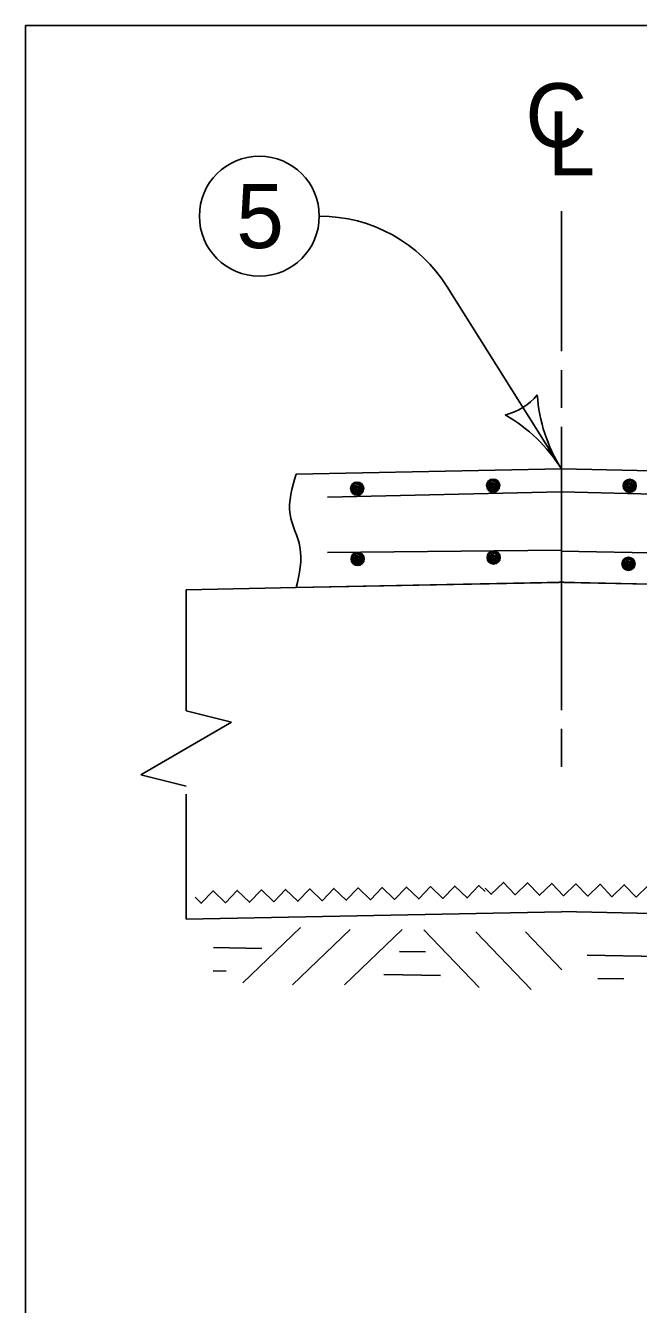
# Model space of a CAD drawing. Extents: x 10130 to 81668, y 5440 to 21644.
# Drawn here: x 17332.5 to 17485.9, y 9624 to 9944 of the extents above; entities that cross this region are included whole.
import ezdxf

# ---------------------------------------------------------------- set-up
doc = ezdxf.new("R2010")
doc.units = 0
for name, color, linetype in [('dsnStdBlockModified', 7, 'Continuous'), ('dsnStdBlockNotModified', 7, 'Continuous'), ('dsnStdBorder', 7, 'Continuous'), ('Level 2', 7, 'Continuous'), ('SheetBorder', 7, 'Continuous')]:
    doc.layers.add(name, color=color, linetype=linetype)

msp = doc.modelspace()

# ---------------------------------------------------------------- linework, layer by layer
at = {"layer": 'dsnStdBlockModified'}
msp.add_line((18198.1, 9797.36), (17466.58, 9812.52), dxfattribs=at)
at = {"layer": 'dsnStdBlockNotModified'}
msp.add_line((17438.06, 9878.61), (17466.63, 9833.07), dxfattribs=at)
for centre, radius, start, end in [((17406.03, 9858.53), 37.81, 32.09, 90), ((17448.73, 9861.6), 15.52, 284.3569, 319.8236), ((17500.66, 9854.41), 40.18, 184.0178, 212.0903), ((17432.59, 9811.72), 40.18, 32.0903, 60.1628)]:
    msp.add_arc(centre, radius, start, end, dxfattribs=at)
at = {"layer": 'dsnStdBorder'}
for p, q in [((17466.62, 9833.07), (17400.24, 9831.73)), ((17466.62, 9833.07), (17400.24, 9831.73)), ((18176.88, 9818.81), (17466.62, 9833.07)), ((17466.62, 9833.07), (18176.88, 9818.81)), ((17466.59, 9827.31), (17408.07, 9826.01)), ((17466.59, 9827.31), (18198.18, 9809.65)), ((17466.59, 9812.75), (17408.06, 9812.12)), ((17400.24, 9803.37), (17372.68, 9802.81)), ((17372.68, 9802.81), (17372.68, 9772.55)), ((17467.19, 9804.71), (17400.24, 9803.37)), ((17400.24, 9803.37), (17466.05, 9804.69)), ((17466.05, 9804.71), (17466.62, 9804.7)), ((17466.05, 9804.71), (18215.16, 9789.67)), ((17466.62, 9804.7), (17467.19, 9804.71)), ((17467.19, 9804.69), (18215.16, 9789.67)), ((17372.68, 9772.55), (17384.03, 9769.72)), ((17384.03, 9769.72), (17372.68, 9763.1)), ((17372.68, 9763.1), (17361.34, 9756.49)), ((17361.34, 9756.49), (17372.68, 9753.65)), ((17372.68, 9751.65), (17372.68, 9720.39)), ((17466.62, 9722.27), (17372.68, 9720.39)), ((17466.62, 9722.28), (18283.21, 9705.89)), ((17401.31, 9718.33), (17386.88, 9704.47)), ((17413.75, 9717.85), (17399.33, 9704)), ((17426.76, 9717.82), (17412.34, 9703.96)), ((17432.17, 9717.71), (17446.03, 9703.29)), ((17445.17, 9717.22), (17459.03, 9702.8)), ((17457.62, 9717.2), (17466.72, 9707.73))]:
    msp.add_line(p, q, dxfattribs=at)
for points in [[(17466.62, 9897.61), (17466.62, 9862.52)], [(17466.63, 9857.8), (17466.63, 9848.34)], [(17466.62, 9843.62), (17466.62, 9772.72)], [(17417.02, 9828.07), (17416.74, 9828.62), (17416.44, 9829.48), (17415.55, 9829.61), (17414.78, 9829.46), (17414.09, 9828.87), (17414.2, 9828.05), (17414.36, 9827.18), (17415.07, 9826.8), (17415.8, 9826.75), (17416.74, 9827.31), (17416.79, 9827.94), (17416.53, 9828.8), (17415.95, 9829.49), (17415.12, 9829.43), (17414.48, 9828.85), (17414.45, 9828.07), (17414.65, 9827.2), (17415.14, 9827.09), (17415.74, 9826.94), (17416.44, 9827.38), (17416.4, 9828.01), (17416.25, 9828.73), (17415.82, 9829.24), (17415.11, 9828.94), (17414.71, 9828.38), (17414.72, 9827.65), (17415.12, 9827.48), (17415.57, 9827.27), (17416.13, 9827.65), (17416.23, 9828.2), (17415.96, 9828.67), (17415.42, 9828.68), (17415.05, 9828.4), (17414.94, 9827.91), (17415.15, 9827.68), (17415.45, 9827.55), (17415.87, 9827.83), (17415.94, 9828.18), (17415.73, 9828.5), (17415.44, 9828.43), (17415.26, 9828.18), (17415.29, 9827.84), (17415.53, 9827.85), (17415.65, 9828.16)], [(17451.05, 9828.84), (17450.77, 9829.38), (17450.47, 9830.24), (17449.58, 9830.37), (17448.81, 9830.22), (17448.12, 9829.63), (17448.23, 9828.81), (17448.39, 9827.94), (17449.1, 9827.55), (17449.83, 9827.51), (17450.77, 9828.06), (17450.82, 9828.7), (17450.57, 9829.56), (17449.98, 9830.25), (17449.16, 9830.19), (17448.51, 9829.61), (17448.48, 9828.83), (17448.68, 9827.97), (17449.17, 9827.85), (17449.77, 9827.7), (17450.47, 9828.14), (17450.43, 9828.77), (17450.28, 9829.49), (17449.85, 9830), (17449.14, 9829.71), (17448.74, 9829.14), (17448.75, 9828.41), (17449.15, 9828.24), (17449.6, 9828.03), (17450.16, 9828.41), (17450.27, 9828.95), (17449.99, 9829.42), (17449.45, 9829.43), (17449.08, 9829.17), (17448.97, 9828.67), (17449.18, 9828.44), (17449.48, 9828.31), (17449.91, 9828.59), (17449.97, 9828.93), (17449.76, 9829.26), (17449.47, 9829.19), (17449.29, 9828.93), (17449.32, 9828.6), (17449.56, 9828.61), (17449.68, 9828.91)], [(17482.2, 9828.81), (17482.47, 9829.35), (17482.78, 9830.21), (17483.67, 9830.33), (17484.44, 9830.18), (17485.12, 9829.6), (17485.01, 9828.77), (17484.85, 9827.91), (17484.14, 9827.52), (17483.4, 9827.47), (17482.47, 9828.03), (17482.42, 9828.67), (17482.68, 9829.53), (17483.26, 9830.22), (17484.09, 9830.16), (17484.73, 9829.57), (17484.77, 9828.79), (17484.56, 9827.93), (17484.07, 9827.82), (17483.47, 9827.66), (17482.77, 9828.11), (17482.82, 9828.74), (17482.97, 9829.46), (17483.4, 9829.96), (17484.11, 9829.67), (17484.5, 9829.1), (17484.5, 9828.37), (17484.09, 9828.21), (17483.64, 9827.99), (17483.09, 9828.38), (17482.98, 9828.92), (17483.26, 9829.39), (17483.79, 9829.4), (17484.16, 9829.13), (17484.27, 9828.63), (17484.06, 9828.4), (17483.76, 9828.28), (17483.34, 9828.55), (17483.27, 9828.9), (17483.49, 9829.23), (17483.77, 9829.16), (17483.95, 9828.9), (17483.92, 9828.56), (17483.69, 9828.57), (17483.56, 9828.88)], [(17451.18, 9810.83), (17450.91, 9811.38), (17450.62, 9812.24), (17449.73, 9812.38), (17448.96, 9812.24), (17448.27, 9811.66), (17448.36, 9810.84), (17448.51, 9809.97), (17449.21, 9809.57), (17449.95, 9809.52), (17450.89, 9810.06), (17450.95, 9810.7), (17450.71, 9811.56), (17450.13, 9812.25), (17449.3, 9812.21), (17448.65, 9811.63), (17448.61, 9810.85), (17448.8, 9809.98), (17449.3, 9809.87), (17449.89, 9809.71), (17450.6, 9810.14), (17450.56, 9810.77), (17450.42, 9811.49), (17450, 9812.01), (17449.28, 9811.72), (17448.88, 9811.16), (17448.87, 9810.43), (17449.27, 9810.26), (17449.72, 9810.04), (17450.29, 9810.41), (17450.4, 9810.96), (17450.13, 9811.43), (17449.59, 9811.45), (17449.22, 9811.18), (17449.1, 9810.69), (17449.31, 9810.46), (17449.61, 9810.33), (17450.03, 9810.59), (17450.11, 9810.94), (17449.89, 9811.27), (17449.6, 9811.21), (17449.42, 9810.95), (17449.45, 9810.61), (17449.69, 9810.62), (17449.82, 9810.93)], [(17417.14, 9810.46), (17416.87, 9811.01), (17416.58, 9811.87), (17415.69, 9812.02), (17414.92, 9811.87), (17414.23, 9811.29), (17414.32, 9810.47), (17414.47, 9809.6), (17415.18, 9809.21), (17415.91, 9809.16), (17416.86, 9809.7), (17416.91, 9810.34), (17416.67, 9811.2), (17416.09, 9811.9), (17415.26, 9811.84), (17414.61, 9811.27), (17414.57, 9810.48), (17414.76, 9809.62), (17415.26, 9809.51), (17415.85, 9809.35), (17416.56, 9809.77), (17416.52, 9810.41), (17416.38, 9811.13), (17415.96, 9811.64), (17415.25, 9811.36), (17414.84, 9810.79), (17414.84, 9810.06), (17415.23, 9809.89), (17415.69, 9809.68), (17416.25, 9810.05), (17416.36, 9810.59), (17416.09, 9811.07), (17415.56, 9811.08), (17415.18, 9810.81), (17415.06, 9810.32), (17415.27, 9810.09), (17415.57, 9809.96), (17415.99, 9810.23), (17416.07, 9810.58), (17415.85, 9810.9), (17415.57, 9810.84), (17415.39, 9810.59), (17415.41, 9810.25), (17415.65, 9810.26), (17415.78, 9810.56)], [(17484.91, 9809.2), (17484.66, 9809.76), (17484.39, 9810.63), (17483.51, 9810.79), (17482.74, 9810.67), (17482.02, 9810.12), (17482.1, 9809.29), (17482.22, 9808.42), (17482.91, 9808), (17483.64, 9807.93), (17484.6, 9808.44), (17484.68, 9809.07), (17484.46, 9809.95), (17483.9, 9810.66), (17483.08, 9810.63), (17482.41, 9810.08), (17482.34, 9809.3), (17482.51, 9808.43), (17483, 9808.3), (17483.59, 9808.12), (17484.31, 9808.53), (17484.29, 9809.16), (17484.17, 9809.89), (17483.77, 9810.41), (17483.04, 9810.15), (17482.62, 9809.6), (17482.59, 9808.87), (17482.99, 9808.68), (17483.43, 9808.45), (17484.01, 9808.81), (17484.14, 9809.35), (17483.88, 9809.83), (17483.34, 9809.86), (17482.96, 9809.61), (17482.83, 9809.12), (17483.03, 9808.88), (17483.33, 9808.74), (17483.76, 9809), (17483.84, 9809.34), (17483.64, 9809.68), (17483.35, 9809.62), (17483.16, 9809.37), (17483.17, 9809.03), (17483.42, 9809.04), (17483.55, 9809.33)], [(17466.05, 9804.69), (17466.05, 9804.71)], [(17467.19, 9804.71), (17467.19, 9804.69)], [(17466.62, 9767.99), (17466.62, 9758.54)], [(17447.53, 9728.18), (17449.01, 9726.64), (17452.1, 9729.6), (17455.06, 9726.52), (17458.15, 9729.48), (17461.11, 9726.4), (17464.19, 9729.36), (17467.16, 9726.28), (17470.24, 9729.24), (17473.21, 9726.16), (17476.29, 9729.12), (17479.26, 9726.03), (17482.34, 9729), (17485.3, 9725.91), (17488.39, 9728.88)], [(17374.95, 9725.87), (17376.49, 9724.39), (17379.45, 9727.47), (17382.54, 9724.51), (17385.5, 9727.6), (17388.59, 9724.63), (17391.55, 9727.72), (17394.63, 9724.75), (17397.6, 9727.84), (17400.68, 9724.87), (17403.65, 9727.96), (17406.73, 9725), (17409.7, 9728.08), (17412.78, 9725.12), (17415.74, 9728.2), (17418.83, 9725.24), (17421.79, 9728.32), (17424.88, 9725.36), (17427.84, 9728.44), (17430.93, 9725.48), (17433.89, 9728.57), (17436.98, 9725.61), (17439.94, 9728.69), (17443.03, 9725.73), (17445.99, 9728.81), (17447.53, 9727.33)], [(17379.59, 9713.29), (17391.62, 9713.05)], [(17426.09, 9712.33), (17432.62, 9712.2)], [(17473.09, 9711.41), (17491.15, 9711.05)], [(17379.47, 9707.49), (17382.74, 9707.42)], [(17422.14, 9706.55), (17436.33, 9706.27)], [(17475.74, 9705.56), (17482.27, 9705.43)]]:
    msp.add_lwpolyline(points, dxfattribs=at)
for centre in [(17415.5, 9828.14), (17449.53, 9828.9), (17483.72, 9828.86), (17415.62, 9810.54), (17449.66, 9810.91), (17483.39, 9809.32)]:
    msp.add_circle(centre, 1.65, dxfattribs=at)
msp.add_spline([(17400.24, 9831.73), (17398.73, 9821.65), (17401.19, 9813.52), (17400.24, 9803.37)], degree=3, dxfattribs=at)
msp.add_spline([(17400.24, 9831.73), (17398.73, 9821.65), (17401.19, 9813.52), (17400.24, 9803.37)], degree=3, dxfattribs=at)
at = {"layer": 'Level 2'}
msp.add_circle((17391.03, 9896.34), 15, dxfattribs=at)
at = {"layer": 'SheetBorder'}
msp.add_lwpolyline([(17332.52, 9944.02), (20467.53, 9944.02), (20467.53, 7924.02), (17332.52, 7924.02)], close=True, dxfattribs=at)

# ---------------------------------------------------------------- texts
at = {"layer": 'dsnStdBlockNotModified'}
for s, p in [('C', (17457.6, 9913.59)), ('L', (17463.14, 9906.52))]:
    msp.add_text(s, height=16, dxfattribs=at).set_placement(p)
at = {"layer": 'Level 2'}
msp.add_text('5', height=16, dxfattribs=at).set_placement((17385.26, 9888.34))

doc.saveas('drawing.dxf')
